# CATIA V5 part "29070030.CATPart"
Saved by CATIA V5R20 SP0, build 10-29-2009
Part number: 29070030
Definition: NONE
Nomenclature: 29070030
Source: Unknown
Description: 29070030
Bounding box of the stored display mesh (mm): x -15 to 44.548, y -49 to 83.548, z -39 to 39
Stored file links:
  C:\Users\Utente\Desktop\IO LAVORO\3D X SITO CF\X SITO\PLASTICA\RF1\29070030.CATPart
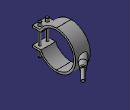
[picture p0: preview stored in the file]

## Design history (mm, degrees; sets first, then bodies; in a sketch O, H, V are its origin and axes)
Body1 "29070030" (main body)
  Solid1: solid without history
